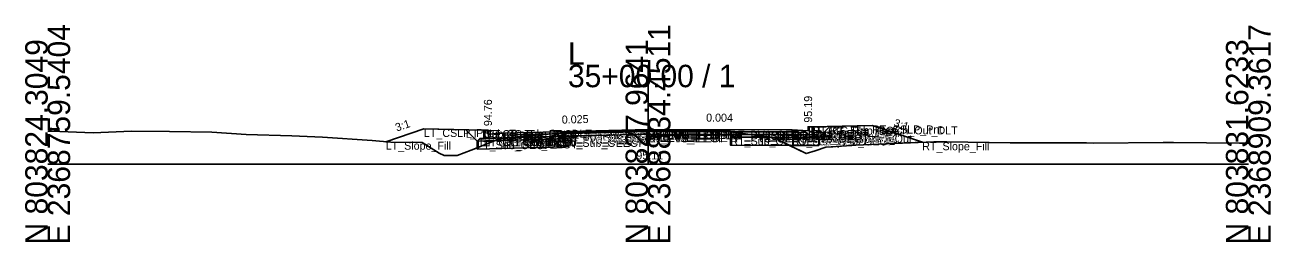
# Model space of a CAD drawing. Extents: x -26 to 8153, y -10 to 9520.
# Drawn here: x 2997.2 to 3152.8, y 490.3 to 517.4 of the extents above; entities that cross this region are included whole.
import ezdxf

# ---------------------------------------------------------------- set-up
doc = ezdxf.new("R2010")
doc.units = 0
for name, color, linetype in [('Exist CMT Pavement', 7, 'Continuous'), ('Exist Cross Section Cell', 7, 'Continuous'), ('Exist XS Center Line Elevation Label', 7, 'Continuous'), ('Exist XS Ground Line', 7, 'Continuous'), ('Prop CMT Conc Surface', 7, 'Continuous'), ('Prop CMT Concrete Structures', 7, 'Continuous'), ('Prop CMT Pvmt Course 1', 7, 'Continuous'), ('Prop CMT Pvmt Course 1 CG', 7, 'Continuous'), ('Prop CMT Pvmt Course 1 Wedge', 7, 'Continuous'), ('Prop CMT Pvmt Course 2', 7, 'Continuous'), ('Prop CMT Pvmt Course 2 Wedge', 7, 'Continuous'), ('Prop CMT Pvmt Course 3', 7, 'Continuous'), ('Prop CMT Pvmt Course 3 Wedge', 7, 'Continuous'), ('Prop CMT Pvmt Surface', 7, 'Continuous'), ('Prop CMT Pvmt Wedge Surface 1', 7, 'Continuous'), ('Prop CMT Pvmt Wedge Surface 2', 7, 'Continuous'), ('Prop CMT Pvmt Wedge Surface 3', 7, 'Continuous'), ('Prop CMT Shallow Undercut', 7, 'Continuous'), ('Prop CMT Shallow Undercut Boundary', 7, 'Continuous'), ('Prop CMT Slope Grass', 7, 'Continuous'), ('Prop CMT Subgrade Earthwork', 7, 'Continuous'), ('Prop XS Earthwork Shape', 7, 'Continuous'), ('Prop XS Hydro Elevations', 7, 'Continuous'), ('Prop XS SE Text', 7, 'Continuous'), ('Prop XS Side Slope Text', 7, 'Continuous'), ('Prop XS Subgrade Earthwork', 7, 'Continuous'), ('Scratch_Level_2', 7, 'Continuous'), ('Scratch_Level_6', 7, 'Continuous')]:
    doc.layers.add(name, color=color, linetype=linetype)

msp = doc.modelspace()

# ---------------------------------------------------------------- linework, layer by layer
at = {"layer": 'Exist CMT Pavement'}
for p, q in [((3064.5, 503.91), (3070.96, 504.05)), ((3070.96, 504.05), (3074.75, 504.12)), ((3074.75, 504.12), (3078.63, 504.08)), ((3078.63, 504.08), (3085.29, 504.05))]:
    msp.add_line(p, q, dxfattribs=at)
at = {"layer": 'Exist Cross Section Cell'}
for p, q in [((3075, 500), (3075, 512.41)), ((3000, 500), (3075, 500)), ((3075, 500), (3150, 500))]:
    msp.add_line(p, q, dxfattribs=at)
at = {"layer": 'Exist XS Ground Line'}
for p, q in [((3000, 504.14), (3000.48, 504.13)), ((3000.48, 504.13), (3005.69, 503.91)), ((3005.69, 503.91), (3010.49, 504.13)), ((3010.49, 504.13), (3015.24, 504.07)), ((3015.24, 504.07), (3020.51, 504.02)), ((3020.51, 504.02), (3024.78, 503.72)), ((3024.78, 503.72), (3030.52, 503.53)), ((3030.52, 503.53), (3034.33, 503.39)), ((3034.33, 503.39), (3040.53, 502.97)), ((3040.53, 502.97), (3042.88, 502.77)), ((3052.92, 501.78), (3056.64, 503.26)), ((3056.64, 503.26), (3060.55, 503.61)), ((3060.55, 503.61), (3064.5, 503.91)), ((3064.5, 503.91), (3070.96, 504.05)), ((3070.96, 504.05), (3074.75, 504.12)), ((3074.75, 504.12), (3078.63, 504.08)), ((3078.63, 504.08), (3085.29, 504.05)), ((3085.29, 504.05), (3090.76, 503.31)), ((3090.76, 503.31), (3094.76, 501.34)), ((3042.88, 502.77), (3046.77, 502.73)), ((3046.77, 502.73), (3048.93, 501.37)), ((3048.93, 501.37), (3049.54, 501.09)), ((3051.17, 501.1), (3052.92, 501.78)), ((3094.76, 501.34), (3095.87, 501.7)), ((3095.87, 501.7), (3097.21, 502.15)), ((3097.21, 502.15), (3100.46, 502.36)), ((3100.46, 502.36), (3100.95, 502.4)), ((3100.95, 502.4), (3110.7, 502.81)), ((3110.7, 502.81), (3112.34, 502.79)), ((3112.34, 502.79), (3120.24, 502.67)), ((3120.24, 502.67), (3120.63, 502.68)), ((3120.63, 502.68), (3129.79, 502.66)), ((3129.79, 502.66), (3130.64, 502.65)), ((3130.64, 502.65), (3139.34, 502.71)), ((3139.34, 502.71), (3140.66, 502.72)), ((3140.66, 502.72), (3148.88, 502.63)), ((3148.88, 502.63), (3150, 502.64)), ((3049.54, 501.09), (3049.99, 501.1)), ((3049.99, 501.1), (3051.17, 501.1))]:
    msp.add_line(p, q, dxfattribs=at)
at = {"layer": 'Prop CMT Conc Surface'}
for points in [[(3095, 504.19), (3095, 504.69), (3095.5, 504.69)], [(3055, 503.76), (3055, 504.26), (3054.5, 504.26)], [(3057, 503.89), (3055, 503.76)], [(3093, 504.28), (3095, 504.19)]]:
    msp.add_lwpolyline(points, dxfattribs=at)
at = {"layer": 'Prop CMT Concrete Structures'}
for points in [[(3093, 504.28), (3095, 504.19), (3095, 504.69), (3095.5, 504.69)], [(3095.5, 504.69), (3095.5, 503.68), (3093, 503.69)], [(3057, 503.89), (3055, 503.76), (3055, 504.26), (3054.5, 504.26)], [(3054.5, 504.26), (3054.5, 503.25), (3057, 503.31)], [(3057, 503.31), (3057, 503.89)], [(3093, 503.69), (3093, 504.28)]]:
    msp.add_lwpolyline(points, dxfattribs=at)
at = {"layer": 'Prop CMT Pvmt Course 1'}
for points in [[(3075, 504.34), (3057, 503.89)], [(3057, 503.89), (3057, 503.64)], [(3057, 503.64), (3064.5, 503.83)], [(3064.5, 503.95), (3075, 504.22)], [(3064.5, 503.83), (3064.5, 503.95)], [(3075, 504.09), (3075, 504.34)], [(3075, 504.34), (3093, 504.28)], [(3075, 504.09), (3075, 504.34)], [(3075, 504.22), (3075, 504.09), (3075, 504.09)], [(3085.29, 504.18), (3075, 504.22)], [(3075, 504.22), (3075, 504.09), (3075, 504.09)], [(3085.29, 504.05), (3085.29, 504.18)], [(3093, 504.03), (3085.29, 504.05)], [(3093, 504.28), (3093, 504.03)]]:
    msp.add_lwpolyline(points, dxfattribs=at)
at = {"layer": 'Prop CMT Pvmt Course 1 CG'}
for points in [[(3057, 503.31), (3054, 503.23), (3053.66, 502.89)], [(3053.66, 502.89), (3057, 502.98)], [(3057, 502.98), (3057, 503.31)], [(3093, 503.69), (3096, 503.68), (3096.33, 503.35)], [(3093, 503.36), (3093, 503.69)], [(3096.33, 503.35), (3093, 503.36)]]:
    msp.add_lwpolyline(points, dxfattribs=at)
at = {"layer": 'Prop CMT Pvmt Course 1 Wedge'}
for points in [[(3075, 504.22), (3064.5, 503.95)], [(3075, 504.22), (3085.29, 504.18)]]:
    msp.add_lwpolyline(points, dxfattribs=at)
at = {"layer": 'Prop CMT Pvmt Course 2'}
for points in [[(3064.5, 503.83), (3057, 503.64)], [(3057, 503.64), (3057, 503.31)], [(3057, 503.31), (3064.5, 503.5)], [(3064.5, 503.5), (3064.5, 503.83)], [(3085.29, 503.72), (3085.29, 504.05)], [(3085.29, 504.05), (3093, 504.03)], [(3093, 503.7), (3085.29, 503.72)], [(3093, 504.03), (3093, 503.7)]]:
    msp.add_lwpolyline(points, dxfattribs=at)
at = {"layer": 'Prop CMT Pvmt Course 2 Wedge'}
for points in [[(3075, 504.09), (3064.5, 503.83)], [(3075, 504.09), (3085.29, 504.05)]]:
    msp.add_lwpolyline(points, dxfattribs=at)
at = {"layer": 'Prop CMT Pvmt Course 3'}
for points in [[(3064.5, 503.5), (3057, 503.31)], [(3057, 503.31), (3057, 502.98)], [(3057, 502.98), (3064.5, 503.17)], [(3064.5, 503.17), (3064.5, 503.5)], [(3085.29, 503.72), (3093, 503.7)], [(3085.29, 503.39), (3085.29, 503.72)], [(3093, 503.36), (3085.29, 503.39)], [(3093, 503.7), (3093, 503.36)]]:
    msp.add_lwpolyline(points, dxfattribs=at)
at = {"layer": 'Prop CMT Pvmt Course 3 Wedge'}
for points in [[(3075, 503.76), (3064.5, 503.5)], [(3075, 503.76), (3085.29, 503.72)]]:
    msp.add_lwpolyline(points, dxfattribs=at)
at = {"layer": 'Prop CMT Pvmt Surface'}
for points in [[(3075, 504.34), (3057, 503.89)], [(3075, 504.34), (3093, 504.28)]]:
    msp.add_lwpolyline(points, dxfattribs=at)
at = {"layer": 'Prop CMT Pvmt Wedge Surface 1'}
for points in [[(3057, 503.64), (3057, 503.89)], [(3064.5, 503.83), (3057, 503.64)], [(3075, 504.22), (3064.5, 503.95)], [(3064.5, 503.95), (3064.5, 503.83)], [(3075, 504.22), (3085.29, 504.18)], [(3085.29, 504.18), (3085.29, 504.05)], [(3085.29, 504.05), (3093, 504.03)], [(3093, 504.03), (3093, 504.28)]]:
    msp.add_lwpolyline(points, dxfattribs=at)
at = {"layer": 'Prop CMT Pvmt Wedge Surface 2'}
for points in [[(3075, 504.09), (3057, 503.64)], [(3057, 503.64), (3057, 503.89)], [(3075, 504.09), (3093, 504.03)], [(3093, 504.03), (3093, 504.28)]]:
    msp.add_lwpolyline(points, dxfattribs=at)
at = {"layer": 'Prop CMT Pvmt Wedge Surface 3'}
for points in [[(3057, 503.31), (3057, 503.89)], [(3075, 503.76), (3057, 503.31)], [(3075, 503.76), (3093, 503.7)], [(3093, 503.7), (3093, 504.28)]]:
    msp.add_lwpolyline(points, dxfattribs=at)
at = {"layer": 'Prop CMT Shallow Undercut'}
for points in [[(3053.66, 502.07), (3053.66, 501.89), (3064.5, 502.17), (3064.5, 503.17), (3055.85, 502.95)], [(3090.3, 503.37), (3085.29, 503.39), (3085.29, 502.39), (3092.68, 502.36), (3090.76, 503.31)]]:
    msp.add_lwpolyline(points, close=True, dxfattribs=at)
at = {"layer": 'Prop CMT Shallow Undercut Boundary'}
for p, q in [((3053.66, 502.89), (3064.5, 503.17)), ((3053.66, 502.89), (3053.66, 501.89)), ((3064.5, 503.17), (3064.5, 502.17)), ((3085.29, 503.39), (3085.29, 502.39)), ((3085.29, 503.39), (3096.33, 503.35)), ((3096.33, 503.35), (3096.33, 502.35)), ((3064.5, 502.17), (3053.66, 501.89)), ((3085.29, 502.39), (3096.33, 502.35))]:
    msp.add_line(p, q, dxfattribs=at)
at = {"layer": 'Prop CMT Slope Grass'}
for points in [[(3054.5, 504.26), (3047, 504.41), (3042.23, 502.82)], [(3095.5, 504.69), (3103, 504.84), (3109.28, 502.75)]]:
    msp.add_lwpolyline(points, dxfattribs=at)
at = {"layer": 'Prop CMT Subgrade Earthwork'}
for points in [[(3093, 503.36), (3096.33, 503.35), (3097.71, 504.73)], [(3057, 502.98), (3053.66, 502.89), (3052.25, 504.31)], [(3064.5, 503.17), (3057, 502.98)], [(3064.5, 503.17), (3064.51, 503.91)], [(3085.29, 503.39), (3085.27, 504.05)], [(3085.29, 503.39), (3093, 503.36)]]:
    msp.add_lwpolyline(points, dxfattribs=at)
at = {"layer": 'Prop XS Earthwork Shape'}
for points in [[(3042.88, 502.77), (3046.77, 502.73), (3048.93, 501.37), (3049.54, 501.09), (3049.99, 501.1), (3051.17, 501.1), (3052.92, 501.78), (3053.66, 502.07), (3053.66, 502.89), (3052.25, 504.31), (3047, 504.41), (3042.23, 502.82)], [(3092.68, 502.36), (3094.76, 501.34), (3095.87, 501.7), (3097.21, 502.15), (3100.46, 502.36), (3100.95, 502.4), (3109.28, 502.75), (3103, 504.84), (3097.71, 504.73), (3096.33, 503.35), (3096.33, 502.35)], [(3064.5, 502.17), (3053.66, 501.89), (3053.66, 502.07), (3055.85, 502.95), (3057, 502.98), (3064.5, 503.17)], [(3055.85, 502.95), (3053.66, 502.89), (3053.66, 502.07)], [(3056.64, 503.26), (3060.55, 503.61), (3064.5, 503.91), (3064.51, 503.91), (3064.5, 503.17), (3057, 502.98), (3055.85, 502.95)], [(3085.29, 503.39), (3090.3, 503.37), (3085.29, 504.05), (3085.27, 504.05)], [(3085.29, 503.39), (3090.3, 503.37), (3090.76, 503.31), (3092.68, 502.36), (3085.29, 502.39)], [(3092.68, 502.36), (3096.33, 502.35), (3096.33, 503.35), (3093, 503.36), (3090.3, 503.37), (3090.76, 503.31)]]:
    msp.add_lwpolyline(points, close=True, dxfattribs=at)
at = {"layer": 'Prop XS Subgrade Earthwork'}
for p, q in [((3053.66, 502.89), (3064.5, 503.17)), ((3096.33, 503.35), (3085.29, 503.39))]:
    msp.add_line(p, q, dxfattribs=at)
at = {"layer": 'Scratch_Level_6'}
for points in [[(3053.66, 502.07), (3053.66, 501.89), (3064.5, 502.17), (3064.5, 503.17), (3055.85, 502.95)], [(3090.3, 503.37), (3085.29, 503.39), (3085.29, 502.39), (3092.68, 502.36), (3090.76, 503.31)]]:
    msp.add_lwpolyline(points, close=True, dxfattribs=at)

# ---------------------------------------------------------------- texts
at = {"layer": 'Exist Cross Section Cell'}
for s, p in [('E 2368759.5404', (3002.8, 490)), ('E 2368834.4511', (3077.8, 490)), ('E 2368909.3617', (3152.8, 490)), ('N 803824.3049', (3000, 490)), ('N 803827.9641', (3075, 490)), ('N 803831.6233', (3150, 490))]:
    msp.add_text(s, height=2.8, rotation=90, dxfattribs=at).set_placement(p)
for s, p in [('L', (3065, 512.41)), ('35+00.00 / 1', (3065, 509.61))]:
    msp.add_text(s, height=2.8, dxfattribs=at).set_placement(p)
at = {"layer": 'Exist XS Center Line Elevation Label'}
msp.add_text('95.11', height=1, dxfattribs=at).set_placement((3073.55, 500.61))
at = {"layer": 'Prop XS Hydro Elevations'}
for s, p in [('94.76', (3055.5, 504.76)), ('95.19', (3095.5, 505.19))]:
    msp.add_text(s, height=1, rotation=90, dxfattribs=at).set_placement(p)
at = {"layer": 'Prop XS SE Text'}
for s, rotation, p in [('0.025', 1.4321, (3064.24, 505.07)), ('0.004', 359.7932, (3082.26, 505.32))]:
    msp.add_text(s, height=1, rotation=rotation, dxfattribs=at).set_placement(p)
at = {"layer": 'Prop XS Side Slope Text'}
for rotation, p in [(18.4349, (3043.62, 504.08)), (341.5651, (3105.62, 504.76))]:
    msp.add_text('3:1', height=1, rotation=rotation, dxfattribs=at).set_placement(p)
at = {"layer": 'Scratch_Level_2'}
for s, p in [('LT_CSLP_Pnt', (3047, 503.41)), ('RT_CG_Top_Face', (3095, 503.69)), ('RT_CG_Top_BOC', (3095.5, 503.69)), ('RT_Sub_Trench_Out_DLT', (3097.71, 503.73)), ('RT_CSLP_Pnt', (3103, 503.84)), ('LT_Slope_Fill', (3042.23, 501.82)), ('LT_Sub_Trench_Out_DLT', (3052.25, 503.31)), ('LT_Sub_OEOP', (3053.66, 501.89)), ('LT_CG1_Shelf_Out', (3054, 502.23)), ('LT_CG_Top_BOC', (3054.5, 503.26)), ('LT_CG_Bot_BOC', (3054.5, 502.25)), ('LT_CG_Top_Face', (3055, 503.26)), ('LT_CG_Top_Gut', (3055, 502.76)), ('LT_PV1_OEOT', (3057, 502.89)), ('LT_PV2_OEOT', (3057, 502.64)), ('LT_PV3_OEOT', (3057, 502.31)), ('LT_CG_Bot_IE', (3057, 502.31)), ('LT_Sub_OEOT', (3057, 501.98)), ('LT_PV1_OEEOP', (3064.5, 502.95)), ('LT_PV_OEEOP_EG', (3064.5, 502.91)), ('LT_PV2_OEEOP', (3064.5, 502.83)), ('LT_PV3_OEEOP', (3064.5, 502.5)), ('LT_Sub_OEEOP', (3064.5, 502.17)), ('LT_PV_Sub_Tie_Out', (3064.51, 502.91)), ('PV1_PGL', (3075, 503.34)), ('RT_PV1_IEEOP', (3075, 503.22)), ('LT_PV1_IEEOP', (3075, 503.22)), ('RT_PV_IEEOP_EG', (3075, 503.11)), ('LT_PV_IEEOP_EG', (3075, 503.11)), ('RT_PV2_IEEOP', (3075, 503.09)), ('LT_PV2_IEEOP', (3075, 503.09)), ('PV2_PGL', (3075, 503.09)), ('RT_PV3_IEEOP', (3075, 502.76)), ('LT_PV3_IEEOP', (3075, 502.76)), ('RT_PV_Sub_Tie_Out', (3085.27, 503.05)), ('RT_PV1_OEEOP', (3085.29, 503.18)), ('RT_PV2_OEEOP', (3085.29, 503.05)), ('RT_PV_OEEOP_EG', (3085.29, 503.05)), ('RT_PV3_OEEOP', (3085.29, 502.72)), ('RT_Sub_OEEOP', (3085.29, 502.39)), ('RT_PV1_OEOT', (3093, 503.28)), ('RT_PV2_OEOT', (3093, 503.03)), ('RT_PV3_OEOT', (3093, 502.7)), ('RT_CG_Bot_IE', (3093, 502.69)), ('RT_Sub_OEOT', (3093, 502.36)), ('RT_CG_Top_Gut', (3095, 503.19)), ('RT_CG_Bot_BOC', (3095.5, 502.68)), ('RT_CG1_Shelf_Out', (3096, 502.68)), ('RT_Sub_OEOP', (3096.33, 502.35)), ('RT_Slope_Fill', (3109.26, 501.75))]:
    msp.add_text(s, height=1, dxfattribs=at).set_placement(p)

doc.saveas('drawing.dxf')
